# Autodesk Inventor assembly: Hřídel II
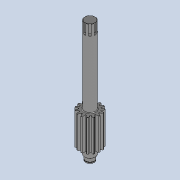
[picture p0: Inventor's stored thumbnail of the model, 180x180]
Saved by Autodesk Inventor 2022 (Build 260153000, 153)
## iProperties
Created: 2025-05
Part Number: Hřídel II
Document SubType Name: Assembly
Designer: jbart
Mass: 1756.11 g
Surface Area: 1642.31 cm^2
Volume: 1756.11 cm^3
Density: 1 g/cm^3
Author: jbart
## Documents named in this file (2)
- C:\Users\jbart\OneDrive\Dokumenty\Inventor\Převodovka navijáku\Hřídel II.iam
- C:\Users\jbart\OneDrive\Dokumenty\Inventor\Převodovka navijáku\Hřídel II\Design Accelerator\Čelní ozubená kola1.iam
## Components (1 placed, 1 different names)
1. Čelní ozubená kola:1 [sub-assembly] — Proti sobě:1, Úhel:1
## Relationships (2: Mate 1, Angle 1)
- Proti sobě:1 [Mate]: Čelní ozubená kola:1
- Úhel:1 [Angle]: Čelní ozubená kola:1
